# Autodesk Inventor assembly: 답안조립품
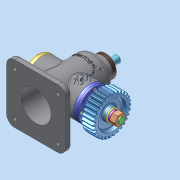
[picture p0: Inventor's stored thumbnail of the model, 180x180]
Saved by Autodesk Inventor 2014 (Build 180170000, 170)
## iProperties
Created: 2026-06
Part Number: 답안조립품
Document SubType Name: Assembly
Designer: dg
Mass: 1454.25 g
Surface Area: 1270.34 cm^2
Volume: 333.435 cm^3
Density: 4.36141 g/cm^3
Author: dg
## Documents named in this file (17)
- C:\Users\dg\Desktop\660603V1004\답안조립품.iam
- C:\Users\dg\Desktop\660603V1004\가져온 구성요소\본체\본체.ipt
- C:\Users\dg\Desktop\660603V1004\가져온 구성요소\6각 구멍붙이 볼트 M3x8\6각 구멍붙이 볼트 M3x8.ipt
- C:\Users\dg\Desktop\660603V1004\가져온 구성요소\6각 구멍붙이 볼트 M4x8\6각 구멍붙이 볼트 M4x8.ipt
- C:\Users\dg\Desktop\660603V1004\가져온 구성요소\6각 너트 M10x1\6각 너트 M10x1.ipt
- C:\Users\dg\Desktop\660603V1004\가져온 구성요소\가이드 부시\가이드 부시.ipt
- C:\Users\dg\Desktop\660603V1004\가져온 구성요소\깊은 홈 볼 베어링 6003\깊은 홈 볼 베어링 6003.ipt
- C:\Users\dg\Desktop\660603V1004\가져온 구성요소\뒷 커버\뒷 커버.ipt
- C:\Users\dg\Desktop\660603V1004\가져온 구성요소\스퍼 기어\스퍼 기어.ipt
- C:\Users\dg\Desktop\660603V1004\가져온 구성요소\스프링 와셔 M10\스프링 와셔 M10.ipt
- C:\Users\dg\Desktop\660603V1004\가져온 구성요소\슬라이더\슬라이더.ipt
- C:\Users\dg\Desktop\660603V1004\가져온 구성요소\앞 커버\앞 커버.ipt
- C:\Users\dg\Desktop\660603V1004\가져온 구성요소\오일 실 17 30 8\오일 실 17 30 8.ipt
- C:\Users\dg\Desktop\660603V1004\가져온 구성요소\캠 축\캠 축.ipt
- C:\Users\dg\Desktop\660603V1004\가져온 구성요소\평와셔 M10\평와셔 M10.ipt
- C:\Users\dg\Desktop\660603V1004\가져온 구성요소\평행 키 3x3x14\평행 키 3x3x14.ipt
- C:\Users\dg\Desktop\660603V1004\가변스프링.ipt
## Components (15 placed, 5 different names)
1. 6각 너트 M10x1:1
2. 가이드 부시:1
3. 가변스프링:1
4. 6각 구멍붙이 볼트 M4x8:3
5. 6각 구멍붙이 볼트 M4x8:4
6. 6각 구멍붙이 볼트 M4x8:5
7. 6각 구멍붙이 볼트 M4x8:6
8. 6각 구멍붙이 볼트 M4x8:2
9. 6각 구멍붙이 볼트 M4x8:7
10. 6각 구멍붙이 볼트 M4x8:8
11. 6각 구멍붙이 볼트 M4x8:9
12. 6각 구멍붙이 볼트 M3x8:1
13. 6각 구멍붙이 볼트 M3x8:2
14. 6각 구멍붙이 볼트 M3x8:3
15. 6각 구멍붙이 볼트 M3x8:4
